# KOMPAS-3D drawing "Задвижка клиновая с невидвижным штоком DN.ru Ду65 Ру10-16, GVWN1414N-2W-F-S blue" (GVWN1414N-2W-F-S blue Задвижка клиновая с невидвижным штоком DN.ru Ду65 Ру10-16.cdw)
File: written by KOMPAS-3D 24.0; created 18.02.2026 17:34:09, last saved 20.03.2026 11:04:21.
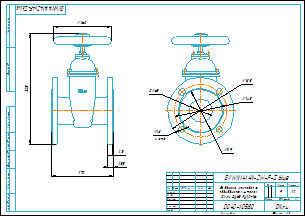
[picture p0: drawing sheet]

Document properties: Автор: R2D2; Форматы листов документа: A3; Полное имя файла: GVWN1414N-2W-F-S blue Задвижка клиновая с невидвижным штоком DN.ru Ду65 Ру10-16.m3d; Масса: 9; Наименование: Задвижка клиновая с невидвижным штоком DN.ru Ду65 Ру10-16; Количество листов документа: 1; Примечание: D040-10580

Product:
- Part/product: Задвижка клиновая с невидвижным штоком DN.ru Ду65 Ру10-16  | designation GVWN1414N-2W-F-S blue
    Масса: 9
    Раздел спецификации: Прочие изделия
    Форматы листов документа: A3
    Примечание: D040-10580

Views: Вид 1, Спереди, Проекционный вид 2
Referenced files in E:\Работа\Зайцев\GVWN1414N-2W-F-S blue Задвижка клиновая с невидвижным штоком DN.ru Ду40-300 Ру10-16\DN65\: GVWN1414N-2W-F-S blue Задвижка клиновая с невидвижным штоком DN.ru Ду65 Ру10-16.m3d
Referenced files in E:\Работа\Зайцев\Для компаса\: чертеж DN.ru А3.cdt
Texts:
  GVWN1414N-2W-F-S blue
  чертеж DN.ru А3.cdt
  Задвижка клиновая с
  невидвижным штоком
  DN.ru Ду65 Ру10-16
  Задвижка клиновая с невидвижным штоком DN.ru Ду65 Ру10-16
  GVWN1414N-2W-F-S blue Задвижка клиновая с невидвижным штоком DN.ru Ду65 Ру10-16
Dimensions and other numbers on the sheet: 0; 3; 2; 4; 170; 15,5; 2,5; 305; 160; 185; 145; 119; 65; 18; 4 отв.; 1:2; 1; 9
